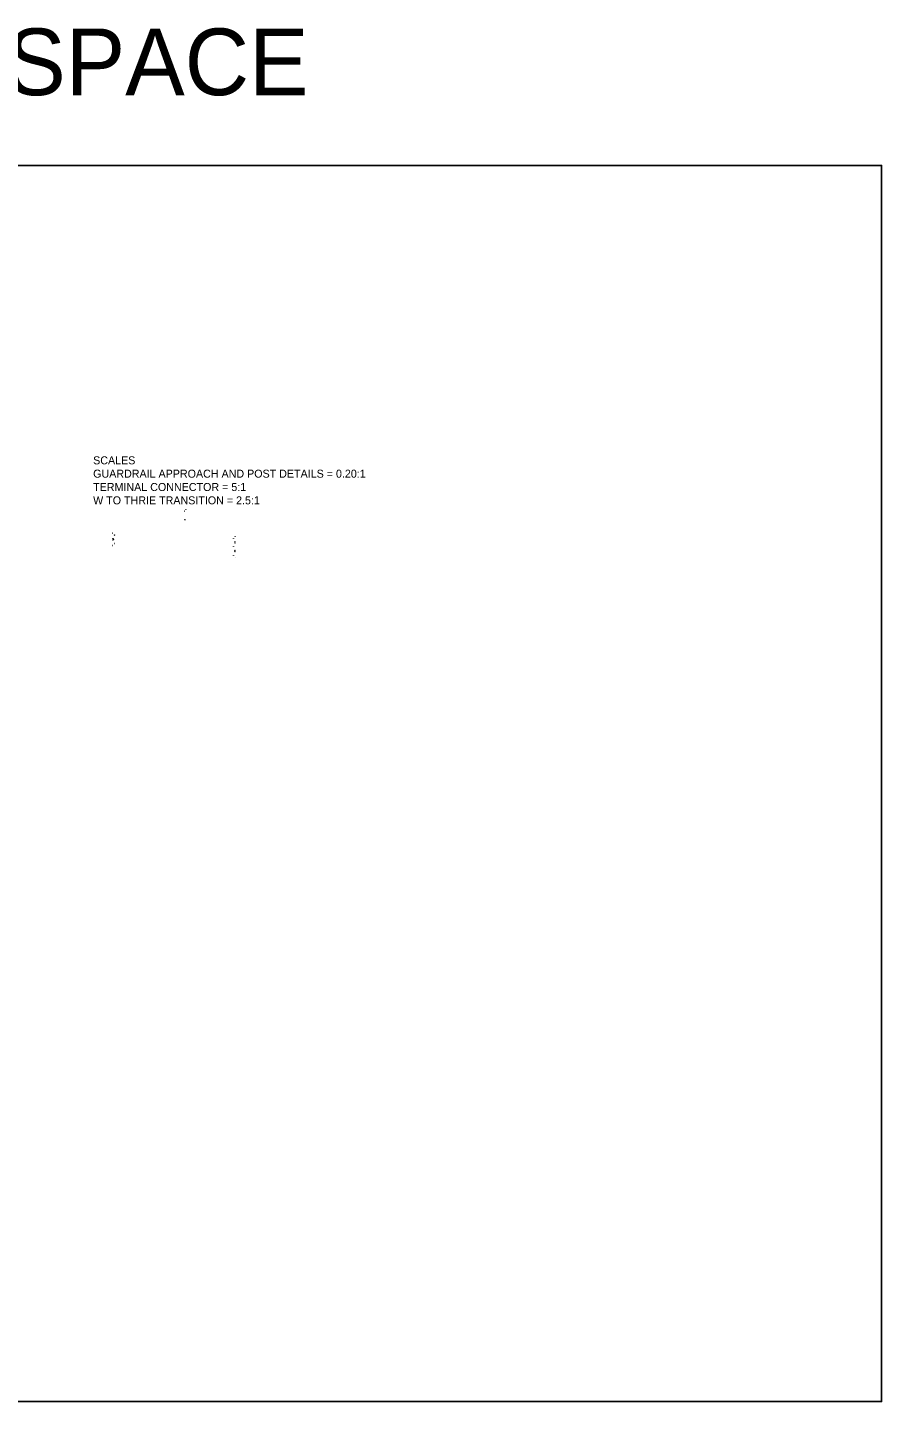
# Model space of a CAD drawing. Extents: x 49991 to 50160, y 49948 to 50051.
# Drawn here: x 50096 to 50160, y 49947.8 to 50050.8 of the extents above; entities that cross this region are included whole.
import ezdxf

# ---------------------------------------------------------------- set-up
doc = ezdxf.new("R2010")
doc.units = 0
for name, color, linetype in [('Default', 7, 'Continuous'), ('Level 2', 7, 'Continuous'), ('Level 3', 7, 'Continuous')]:
    doc.layers.add(name, color=color, linetype=linetype)

# ---------------------------------------------------------------- blocks, each defined once
blk = doc.blocks.new('SW_CENTERMARK18')
at = {"layer": 'Default'}
for q in [(0.607, 3.173), (0.609, 3.175), (0.609, 3.17), (0.612, 3.173)]:
    blk.add_line((0.609, 3.173), q, dxfattribs=at)
blk = doc.blocks.new('SW_CENTERMARK19')
at = {"layer": 'Default'}
for q in [(0.57, 3.129), (0.573, 3.132), (0.573, 3.127), (0.575, 3.129)]:
    blk.add_line((0.573, 3.129), q, dxfattribs=at)
blk = doc.blocks.new('SW_CENTERMARK20')
at = {"layer": 'Default'}
for q in [(0.602, 3.046), (0.605, 3.049), (0.605, 3.044), (0.607, 3.046)]:
    blk.add_line((0.605, 3.046), q, dxfattribs=at)
blk = doc.blocks.new('SW_CENTERMARK21')
at = {"layer": 'Default'}
for q in [(0.602, 3.018), (0.605, 3.021), (0.605, 3.016), (0.607, 3.018)]:
    blk.add_line((0.605, 3.018), q, dxfattribs=at)
blk = doc.blocks.new('SW_CENTERMARK22')
at = {"layer": 'Default'}
for q in [(0.57, 2.935), (0.573, 2.938), (0.573, 2.933), (0.575, 2.935)]:
    blk.add_line((0.573, 2.935), q, dxfattribs=at)
blk = doc.blocks.new('SW_CENTERMARK23')
at = {"layer": 'Default'}
for q in [(0.602, 2.852), (0.605, 2.855), (0.605, 2.85), (0.607, 2.852)]:
    blk.add_line((0.605, 2.852), q, dxfattribs=at)
blk = doc.blocks.new('SW_CENTERMARK24')
at = {"layer": 'Default'}
for q in [(0.57, 2.741), (0.573, 2.744), (0.573, 2.739), (0.575, 2.741)]:
    blk.add_line((0.573, 2.741), q, dxfattribs=at)
blk = doc.blocks.new('SW_CENTERMARK25')
at = {"layer": 'Default'}
for q in [(0.607, 2.698), (0.609, 2.7), (0.609, 2.695), (0.612, 2.698)]:
    blk.add_line((0.609, 2.698), q, dxfattribs=at)
blk = doc.blocks.new('SW_CENTERMARK26')
at = {"layer": 'Default'}
for q in [(0.605, 2.827), (0.602, 2.824), (0.605, 2.822), (0.607, 2.824)]:
    blk.add_line((0.605, 2.824), q, dxfattribs=at)
blk = doc.blocks.new('SW_CENTERMARK27')
at = {"layer": 'Default'}
for q in [(3.445, 3.173), (3.447, 3.175), (3.447, 3.17), (3.45, 3.173)]:
    blk.add_line((3.447, 3.173), q, dxfattribs=at)
blk = doc.blocks.new('SW_CENTERMARK28')
at = {"layer": 'Default'}
for q in [(3.482, 3.129), (3.484, 3.132), (3.484, 3.127), (3.487, 3.129)]:
    blk.add_line((3.484, 3.129), q, dxfattribs=at)
blk = doc.blocks.new('SW_CENTERMARK29')
at = {"layer": 'Default'}
for q in [(3.449, 3.046), (3.452, 3.049), (3.452, 3.044), (3.454, 3.046)]:
    blk.add_line((3.452, 3.046), q, dxfattribs=at)
blk = doc.blocks.new('SW_CENTERMARK30')
at = {"layer": 'Default'}
for q in [(3.445, 2.892), (3.447, 2.894), (3.447, 2.889), (3.45, 2.892)]:
    blk.add_line((3.447, 2.892), q, dxfattribs=at)
blk = doc.blocks.new('SW_CENTERMARK31')
at = {"layer": 'Default'}
for q in [(3.482, 2.935), (3.484, 2.938), (3.484, 2.933), (3.487, 2.935)]:
    blk.add_line((3.484, 2.935), q, dxfattribs=at)
blk = doc.blocks.new('SW_CENTERMARK32')
at = {"layer": 'Default'}
for q in [(3.449, 3.018), (3.452, 3.021), (3.452, 3.016), (3.454, 3.018)]:
    blk.add_line((3.452, 3.018), q, dxfattribs=at)
blk = doc.blocks.new('SW_CENTERMARK33')
at = {"layer": 'Default'}
for q in [(3.465, 3.032), (3.468, 3.035), (3.468, 3.03), (3.47, 3.032)]:
    blk.add_line((3.468, 3.032), q, dxfattribs=at)
blk = doc.blocks.new('SW_CENTERMARK34')
at = {"layer": 'Default'}
for q in [(3.465, 3.032), (3.468, 3.035), (3.468, 3.03), (3.47, 3.032)]:
    blk.add_line((3.468, 3.032), q, dxfattribs=at)
blk = doc.blocks.new('SW_CENTERMARK35')
at = {"layer": 'Default'}
for q in [(4.623, 3.173), (4.626, 3.175), (4.626, 3.17), (4.628, 3.173)]:
    blk.add_line((4.626, 3.173), q, dxfattribs=at)
blk = doc.blocks.new('SW_CENTERMARK36')
at = {"layer": 'Default'}
for q in [(4.586, 3.129), (4.589, 3.132), (4.589, 3.127), (4.591, 3.129)]:
    blk.add_line((4.589, 3.129), q, dxfattribs=at)
blk = doc.blocks.new('SW_CENTERMARK37')
at = {"layer": 'Default'}
for q in [(4.602, 2.935), (4.605, 2.938), (4.605, 2.933), (4.607, 2.935)]:
    blk.add_line((4.605, 2.935), q, dxfattribs=at)
blk = doc.blocks.new('SW_CENTERMARK38')
at = {"layer": 'Default'}
for q in [(4.602, 2.935), (4.605, 2.938), (4.605, 2.933), (4.607, 2.935)]:
    blk.add_line((4.605, 2.935), q, dxfattribs=at)
blk = doc.blocks.new('SW_CENTERMARK39')
at = {"layer": 'Default'}
for q in [(4.602, 2.935), (4.605, 2.938), (4.605, 2.933), (4.607, 2.935)]:
    blk.add_line((4.605, 2.935), q, dxfattribs=at)
blk = doc.blocks.new('SW_CENTERMARK40')
at = {"layer": 'Default'}
for q in [(4.602, 2.935), (4.605, 2.938), (4.605, 2.933), (4.607, 2.935)]:
    blk.add_line((4.605, 2.935), q, dxfattribs=at)
blk = doc.blocks.new('SW_CENTERMARK41')
at = {"layer": 'Default'}
for q in [(4.602, 2.935), (4.605, 2.938), (4.605, 2.933), (4.607, 2.935)]:
    blk.add_line((4.605, 2.935), q, dxfattribs=at)
blk = doc.blocks.new('SW_CENTERMARK42')
at = {"layer": 'Default'}
for q in [(4.602, 2.935), (4.605, 2.938), (4.605, 2.933), (4.607, 2.935)]:
    blk.add_line((4.605, 2.935), q, dxfattribs=at)
blk = doc.blocks.new('SW_CENTERMARK43')
at = {"layer": 'Default'}
for q in [(4.602, 2.935), (4.605, 2.938), (4.605, 2.933), (4.607, 2.935)]:
    blk.add_line((4.605, 2.935), q, dxfattribs=at)

msp = doc.modelspace()

# ---------------------------------------------------------------- linework, layer by layer
at = {"layer": 'Level 3'}
msp.add_lwpolyline([(50028.82, 50040.47), (50160.03, 50040.47), (50160.03, 49947.79), (50028.82, 49947.79)], close=True, dxfattribs=at)

# ---------------------------------------------------------------- block references
at = {"layer": 'Default', "xscale": 3.2808398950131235, "yscale": 3.280839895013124}
for name, p in [('SW_CENTERMARK35', (50092.68, 50004.28)), ('SW_CENTERMARK36', (50092.68, 50004.28)), ('SW_CENTERMARK37', (50092.68, 50004.28)), ('SW_CENTERMARK38', (50092.68, 50004.28)), ('SW_CENTERMARK39', (50092.68, 50004.28)), ('SW_CENTERMARK40', (50092.68, 50004.28)), ('SW_CENTERMARK41', (50092.68, 50004.28)), ('SW_CENTERMARK42', (50092.68, 50004.28)), ('SW_CENTERMARK43', (50092.68, 50004.28)), ('SW_CENTERMARK27', (50091.06, 50002.49)), ('SW_CENTERMARK28', (50091.06, 50002.49)), ('SW_CENTERMARK18', (50109.55, 50002.25)), ('SW_CENTERMARK30', (50091.06, 50002.49)), ('SW_CENTERMARK29', (50091.06, 50002.49)), ('SW_CENTERMARK32', (50091.06, 50002.49)), ('SW_CENTERMARK33', (50091.06, 50002.49)), ('SW_CENTERMARK34', (50091.06, 50002.49)), ('SW_CENTERMARK31', (50091.06, 50002.49)), ('SW_CENTERMARK19', (50109.55, 50002.25)), ('SW_CENTERMARK22', (50109.55, 50002.25)), ('SW_CENTERMARK20', (50109.55, 50002.25)), ('SW_CENTERMARK21', (50109.55, 50002.25)), ('SW_CENTERMARK23', (50109.55, 50002.25)), ('SW_CENTERMARK24', (50109.55, 50002.25)), ('SW_CENTERMARK26', (50109.55, 50002.25)), ('SW_CENTERMARK25', (50109.55, 50002.25))]:
    msp.add_blockref(name, p, dxfattribs=at)

# ---------------------------------------------------------------- texts
at = {"layer": 'Level 2'}
for s, p in [('SCALES', (50100.9, 50018.06)), ('GUARDRAIL APPROACH AND POST DETAILS = 0.20:1', (50100.9, 50017.06)), ('TERMINAL CONNECTOR = 5:1', (50100.9, 50016.06)), ('W TO THRIE TRANSITION = 2.5:1', (50100.9, 50015.06))]:
    msp.add_text(s, height=0.6, dxfattribs=at).set_placement(p)
at = {"layer": 'Level 3'}
msp.add_text('WORK SPACE', height=5, dxfattribs=at).set_placement((50071.73, 50045.74))

doc.saveas('drawing.dxf')
